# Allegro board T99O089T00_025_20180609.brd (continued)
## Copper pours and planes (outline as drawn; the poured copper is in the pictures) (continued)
(no net) on T18: 49.51,109.04 56.87,109.04 57.38,108.53 57.38,107.13 57.13,106.88 49.64,106.88 49.38,107.13 49.38,108.91
(no net) on T18: 49.08,90.08 45.96,90.08 45.36,89.49 45.36,79.55 43.2,77.39 43.2,68.43 44.11,67.52 51.7,67.52 52,67.82 52,76.89 49.45,79.44 49.45,89.72
(no net) on T18: 48.15,186.53 48.42,186.26 55.27,186.26 56.46,187.44 56.46,190.62 58.35,192.51 59.89,194.05 72.24,206.4 86.28,206.4 87.52,207.64 104.05,207.64 105.12,208.7 105.12,211.35 104.73,211.75 65.69,211.75 52.56,198.61 52.56,197.71 48.15,193.29
(no net) on T18: 7.08,90.33 7.08,97.55 8.02,98.48 25.32,98.48 25.72,98.09 25.72,90.41 25.47,90.16 7.26,90.16
(no net) on T18: 152.27,138.05 164.08,138.05 164.97,137.16 164.97,123.83 163.19,122.05 153.42,122.05 150.88,124.59 150.88,127.38 151.68,128.18 151.68,129.31 151.87,129.5 153.13,129.5 153.27,129.36 153.27,128.52 154.52,127.27 158.95,127.27 159.49,127.82 159.49,133.28 158.96,133.8 158.9,133.87 152.88,133.87 151.86,134.88 151.86,137.64
(no net) on T18: 57.13,104.72 56.87,104.47 50.14,104.47 49.89,104.72 49.89,106.37 50.27,106.75 57.13,106.75
(no net) on T18: 196.34,131.32 198.75,128.91 202.31,128.91 204.47,126.75 204.47,125.86 204.22,125.6 196.22,125.6 194.56,127.25 194.56,131.65 194.59,131.67 194.59,132.23 194.82,132.46 196.22,132.46 196.34,132.33
(no net) on G19: 1.39,0.51 1,0.51 0.65,0.65 0.51,1 0.51,207.78 0.51,208.98 0.65,209.33 1,209.47 2.2,209.47 38.51,209.47 39.55,209.91 39.99,210.95 39.99,214.03 39.99,214.03 39.99,214.83 40.14,215.18 40.48,215.32 41.29,215.32 312.38,215.32 312.5,215.32 312.85,215.18 312.99,214.83 312.99,14.06 312.88,14.06 312.17,13.76 311.87,13.05 311.87,10.55 312.17,9.84 312.88,9.54 312.99,9.54 312.99,5.57 312.99,4.97 312.85,4.62 312.5,4.48 311.9,4.48 288.55,4.48 288.55,4.11 83.6,4.11 82.91,4.11 82.56,4.25 82.42,4.6 82.42,5.29 82.42,10.48 81.97,11.52 80.94,11.96 63.41,11.96 62.64,11.73 62.1,11.14 43.51,11.14 42.47,10.7 42.03,9.66 42.03,1.47 42.03,1 41.89,0.65 41.54,0.51 41.07,0.51 ; 19 cut-outs
5P49V_VDDO on BOTTOM (solid shape): 145.78,118.35 145.78,117.03 145.74,116.98 143.4,116.98 143.18,117.28 142.9,117.51 142.9,118.39 143.06,118.56 145.57,118.56
5P49V_VDDO on T05 (solid shape): outline of 468 points within 137.63,117.83 144.35,124.8
DDR3_BMC_MVREF on BOTTOM (solid shape): outline of 673 points within 50.02,109.18 58,113.68
QSFP28_P1_VCC on TOP (solid shape): 310.57,79.61 310.75,79.54 310.82,79.36 310.82,72.31 310.71,72.19 309.56,72.19 309.4,72.35 309.4,79.36 309.48,79.54 309.66,79.61
QSFP28_P1_VCCRX on TOP (solid shape): 303.71,79.6 303.89,79.53 303.96,79.35 303.96,73.1 303.96,73.1 303.96,71.72 303.78,71.54 302.71,71.54 302.54,71.7 302.54,79.35 302.61,79.53 302.79,79.6
QSFP28_P2_VCC on TOP (solid shape): 294.28,79.22 294.46,79.15 294.53,78.97 294.53,72.19 294.86,71.87 294.86,71.27 294.61,71.02 293.27,71.02 293.11,71.18 293.11,78.97 293.18,79.15 293.36,79.22
QSFP28_P2_VCCTX on TOP (solid shape): 301.3,79.31 301.48,79.23 301.55,79.05 301.55,71.43 301.24,71.12 299.99,71.12 299.79,71.32 299.79,72.08 300.13,72.42 300.13,79.05 300.21,79.23 300.39,79.31
SFP+_P00_RXVCC on TOP (solid shape): 99.84,71.07 99.84,63.85 99.28,63.29 96.88,63.29 96.84,63.32 96.84,66.06 98.02,67.24 98.02,71.15 98.12,71.25 99.66,71.25
SFP+_P00_TXVCC on TOP (solid shape): 90.47,70.79 90.47,66.93 91.18,66.22 91.18,63.3 90.99,63.11 88.95,63.11 88.67,63.39 88.67,70.79 88.72,70.85 90.41,70.85
SFP+_P01_RXVCC on BOTTOM (solid shape): outline of 1433 points within 83.5,47.07 91.39,70.85
SFP+_P01_TXVCC on BOTTOM (solid shape): outline of 1321 points within 91.32,45.4 99.84,71.25
SFP+_P02_RXVCC on TOP (solid shape): 111.92,71.07 111.92,63.85 111.35,63.29 108.96,63.29 108.92,63.32 108.92,66.06 110.1,67.24 110.1,71.15 110.2,71.25 111.74,71.25
SFP+_P02_TXVCC on TOP (solid shape): 102.55,71.05 102.55,66.93 103.26,66.22 103.26,63.3 103.07,63.11 101.03,63.11 100.75,63.39 100.75,71.01 100.9,71.16 102.43,71.16
SFP+_P03_RXVCC on BOTTOM (solid shape): outline of 1409 points within 98.38,47.05 105.67,71.16
SFP+_P03_TXVCC on BOTTOM (solid shape): outline of 1297 points within 105.58,45.11 111.92,71.25
SFP+_P04_RXVCC on TOP (solid shape): 123.99,70.82 123.99,63.22 123.71,62.93 121.09,62.93 121,63.02 121,65.81 122.17,66.99 122.17,70.89 122.28,71 123.82,71
SFP+_P04_TXVCC on TOP (solid shape): 114.63,70.79 114.63,66.68 115.34,65.97 115.34,63.14 115.21,63.01 113.06,63.01 112.82,63.24 112.82,70.76 112.97,70.91 114.51,70.91
SFP+_P05_RXVCC on BOTTOM (solid shape): outline of 1568 points within 112.82,46.82 119.94,70.91
SFP+_P05_TXVCC on BOTTOM (solid shape): outline of 1262 points within 119.8,44.95 127.25,71
SFP+_P06_RXVCC on TOP (solid shape): 136.07,70.82 136.07,63.22 135.78,62.93 133.17,62.93 133.08,63.02 133.08,65.81 134.25,66.99 134.25,70.89 134.35,71 135.89,71
SFP+_P06_TXVCC on TOP (solid shape): 126.7,70.79 126.7,66.68 127.41,65.97 127.41,63.14 127.26,62.99 125.15,62.99 124.9,63.24 124.9,70.76 125.05,70.91 126.59,70.91
SFP+_P07_RXVCC on BOTTOM (solid shape): outline of 1524 points within 124.9,46.62 134.25,70.91
SFP+_P07_TXVCC on BOTTOM (solid shape): outline of 1267 points within 133.08,44.79 139.72,71
SFP+_P08_RXVCC on TOP (solid shape): 152.01,71.33 152.01,64.11 151.45,63.54 149.05,63.54 149.02,63.58 149.02,66.32 150.19,67.49 150.19,71.4 150.3,71.5 151.84,71.5
SFP+_P08_TXVCC on TOP (solid shape): 142.65,71.3 142.65,67.19 143.36,66.48 143.36,63.55 143.17,63.36 141.12,63.36 140.84,63.64 140.84,71.27 140.99,71.42 142.53,71.42
SFP+_P09_RXVCC on BOTTOM (solid shape): outline of 1549 points within 140.84,47.07 148.42,71.42
SFP+_P09_TXVCC on BOTTOM (solid shape): outline of 1151 points within 148.35,45.4 153.73,71.5
SFP+_P10_RXVCC on TOP (solid shape): 164.09,70.94 164.09,63.72 163.53,63.16 161.13,63.16 161.1,63.2 161.1,65.94 162.27,67.11 162.27,71.02 162.37,71.12 163.91,71.12
SFP+_P10_TXVCC on TOP (solid shape): 154.72,71.3 154.72,67.19 155.43,66.48 155.43,63.55 155.24,63.36 153.2,63.36 152.92,63.64 152.92,71.27 153.07,71.42 154.61,71.42
SFP+_P11_RXVCC on BOTTOM (solid shape): outline of 1443 points within 152.92,47.05 162.69,71.42
SFP+_P11_TXVCC on BOTTOM (solid shape): outline of 1192 points within 161.1,45.11 167.75,71.12
SFP+_P12_RXVCC on TOP (solid shape): 176.17,71.07 176.17,63.47 175.88,63.19 173.26,63.19 173.17,63.28 173.17,66.06 174.35,67.24 174.35,71.15 174.45,71.25 175.99,71.25
SFP+_P12_TXVCC on TOP (solid shape): 166.8,71.05 166.8,66.93 167.51,66.22 167.51,63.39 167.38,63.26 165.23,63.26 165,63.5 165,71.01 165.15,71.16 166.69,71.16
SFP+_P13_RXVCC on BOTTOM (solid shape): outline of 1268 points within 165,46.82 176.96,71.16
SFP+_P13_TXVCC on BOTTOM (solid shape): outline of 1137 points within 173.17,44.95 182.23,71.25
SFP+_P14_RXVCC on TOP (solid shape): 188.25,71.07 188.25,63.53 187.99,63.27 185.32,63.27 185.25,63.34 185.25,66.06 186.43,67.24 186.43,71.15 186.53,71.25 188.07,71.25
SFP+_P14_TXVCC on TOP (solid shape): 178.88,71.05 178.88,66.93 179.59,66.22 179.59,63.4 179.44,63.25 177.32,63.25 177.07,63.5 177.07,71.01 177.22,71.16 178.76,71.16
SFP+_P15_RXVCC on BOTTOM (solid shape): outline of 1546 points within 177.07,46.62 191.27,71.16
SFP+_P15_TXVCC on BOTTOM (solid shape): outline of 1296 points within 185.25,44.79 198.81,71.25
SFP+_P16_RXVCC on TOP (solid shape): 216.12,71.33 216.12,64.11 215.56,63.54 213.16,63.54 213.12,63.58 213.12,66.32 214.3,67.49 214.3,71.4 214.4,71.5 215.94,71.5
SFP+_P16_TXVCC on TOP (solid shape): 206.75,71.3 206.75,67.19 207.46,66.48 207.46,63.55 207.27,63.36 205.23,63.36 204.95,63.64 204.95,71.27 205.1,71.42 206.64,71.42
SFP+_P17_RXVCC on BOTTOM (solid shape): 206.7,71.06 206.7,66.94 207.41,66.23 207.41,63.34 207.36,63.29 205.08,63.29 204.9,63.47 204.9,71.02 205.05,71.17 206.59,71.17
SFP+_P17_TXVCC on BOTTOM (solid shape): 216.12,71.33 216.12,63.51 215.92,63.31 213.12,63.31 213.12,66.32 214.3,67.49 214.3,71.4 214.4,71.5 215.94,71.5
SFP+_P18_RXVCC on TOP (solid shape): 228.2,70.94 228.2,63.72 227.63,63.16 225.24,63.16 225.2,63.2 225.2,65.94 226.38,67.11 226.38,71.02 226.48,71.12 228.02,71.12
SFP+_P18_TXVCC on TOP (solid shape): 218.83,71.3 218.83,67.19 219.54,66.48 219.54,63.55 219.35,63.36 217.31,63.36 217.03,63.64 217.03,71.27 217.18,71.42 218.71,71.42
SFP+_P19_RXVCC on BOTTOM (solid shape): 218.83,71.3 218.83,67.19 219.54,66.48 219.54,63.19 219.51,63.12 219.43,63.09 219.01,62.96 218.86,62.55 218.83,62.47 218.75,62.44 217.32,62.44 217.03,62.74 217.03,71.27 217.18,71.42 218.71,71.42
SFP+_P19_TXVCC on BOTTOM (solid shape): 228.2,70.94 228.2,61.68 227.87,61.35 225.4,61.35 225.2,61.55 225.2,62.57 225.68,62.57 225.68,62.51 225.69,62.44 225.7,62.38 225.73,62.32 225.76,62.27 225.79,62.21 225.84,62.17 225.89,62.13 225.94,62.09 226,62.06 226.06,62.04 226.12,62.03 226.19,62.03 226.25,62.03 226.31,62.04 226.37,62.06 226.43,62.09 226.49,62.13 226.54,62.17 226.58,62.21 226.62,62.27 226.65,62.32 226.67,62.38 226.69,62.44 226.7,62.51 226.7,62.57 226.69,62.63 226.67,62.7 226.65,62.75 226.62,62.81 226.58,62.86 226.54,62.91 226.49,62.95 226.43,62.98 226.37,63.01 226.31,63.03 226.25,63.04 226.19,63.05 226.12,63.04 226.06,63.03 226,63.01 225.94,62.98 225.89,62.95 225.84,62.91 225.79,62.86 225.76,62.81 225.73,62.75 225.7,62.7 225.69,62.63 225.68,62.57 225.2,62.57 225.2,65.94 226.38,67.11 226.38,71.02 226.48,71.12 228.02,71.12
SFP+_P20_RXVCC on TOP (solid shape): 240.27,71.07 240.27,63.47 239.99,63.19 237.37,63.19 237.28,63.28 237.28,66.06 238.45,67.24 238.45,71.15 238.56,71.25 240.1,71.25
SFP+_P20_TXVCC on TOP (solid shape): 230.91,71.05 230.91,66.93 231.62,66.22 231.62,63.39 231.49,63.26 229.34,63.26 229.1,63.5 229.1,71.01 229.25,71.16 230.79,71.16
SFP+_P21_RXVCC on BOTTOM (solid shape): 230.91,71.05 230.91,66.93 231.62,66.22 231.62,63.05 231.57,62.97 231.48,62.96 230.78,62.49 231.48,62.01 231.57,62 231.62,61.92 231.62,61.09 231.27,60.75 229.49,60.75 229.1,61.14 229.1,71.01 229.25,71.16 230.79,71.16
SFP+_P21_TXVCC on BOTTOM (solid shape): 240.27,71.07 240.27,61.93 239.75,61.41 237.62,61.41 237.28,61.75 237.28,61.88 237.31,61.95 237.38,61.98 237.89,62.49 237.38,62.99 237.31,63.02 237.28,63.1 237.28,66.06 238.45,67.24 238.45,71.15 238.56,71.25 240.1,71.25
SFP+_P22_RXVCC on TOP (solid shape): 252.35,71.07 252.35,63.53 252.09,63.27 249.42,63.27 249.36,63.34 249.36,66.06 250.53,67.24 250.53,71.15 250.63,71.25 252.17,71.25
SFP+_P22_TXVCC on TOP (solid shape): 242.98,71.05 242.98,66.93 243.69,66.22 243.69,63.4 243.54,63.25 241.43,63.25 241.18,63.5 241.18,71.01 241.33,71.16 242.87,71.16
SFP+_P23_RXVCC on BOTTOM (solid shape): 242.97,71.05 242.97,66.93 243.68,66.22 243.68,62.23 243.41,61.96 241.44,61.96 241.17,62.23 241.17,71.01 241.32,71.16 242.86,71.16
SFP+_P23_TXVCC on BOTTOM (solid shape): 252.34,71.07 252.34,63.87 252.36,63.85 252.36,62.57 252.09,62.3 249.62,62.3 249.34,62.58 249.34,66.06 250.52,67.24 250.52,71.15 250.62,71.25 252.16,71.25
SFP+_P24_RXVCC on TOP (solid shape): 264.51,70.99 264.51,63.77 263.95,63.21 261.55,63.21 261.52,63.24 261.52,65.98 262.69,67.16 262.69,71.06 262.8,71.17 264.34,71.17
SFP+_P24_TXVCC on TOP (solid shape): 255.15,71.35 255.15,67.23 255.86,66.52 255.86,63.6 255.67,63.41 253.62,63.41 253.34,63.69 253.34,71.31 253.49,71.46 255.03,71.46
SFP+_P25_RXVCC on BOTTOM (solid shape): 255.15,71.35 255.15,67.23 255.86,66.52 255.86,62.23 255.34,61.72 253.6,61.72 253.34,61.97 253.34,71.31 253.49,71.46 255.03,71.46
SFP+_P25_TXVCC on BOTTOM (solid shape): 264.51,70.99 264.51,63.53 264.51,61.98 264.03,61.5 261.7,61.5 261.52,61.69 261.52,62.21 261.56,62.21 261.93,62.66 261.56,63.11 261.52,63.12 261.52,65.98 262.69,67.16 262.69,71.06 262.8,71.17 264.34,71.17
SFP+_P26_RXVCC on TOP (solid shape): 276.59,70.99 276.59,63.77 276.03,63.21 273.63,63.21 273.6,63.24 273.6,65.98 274.77,67.16 274.77,71.06 274.82,71.11 276.47,71.11
SFP+_P26_TXVCC on TOP (solid shape): 267.22,71.35 267.22,67.23 267.93,66.52 267.93,63.6 267.74,63.41 265.7,63.41 265.42,63.69 265.42,71.31 265.57,71.46 267.11,71.46
SFP+_P27_RXVCC on BOTTOM (solid shape): 267.22,71.35 267.22,67.23 267.93,66.52 267.93,63.3 267.89,63.21 267.79,63.2 267.15,62.78 267.79,62.37 267.89,62.36 267.93,62.27 267.93,61.89 267.65,61.61 265.72,61.61 265.42,61.92 265.42,71.31 265.57,71.46 267.11,71.46
SFP+_P27_TXVCC on BOTTOM (solid shape): 276.59,70.99 276.59,62 276.28,61.69 274.33,61.69 273.83,62.19 273.8,62.28 273.87,62.36 274.15,62.87 273.7,63.24 273.63,63.27 273.6,63.34 273.6,65.98 274.77,67.16 274.77,71.06 274.87,71.17 276.41,71.17
VFLT_P1V8_JA_VDD on BOTTOM (solid shape): 162.41,139.91 162.41,136.51 162.41,135.59 162.41,134.87 162.28,134.75 161.01,134.75 160.9,134.85 160.9,139.84 161.05,139.99 162.33,139.99
VFLT_P1V8_JA_VDD on T07 (solid shape): outline of 489 points within 155.13,125.03 162.69,135.95
VFLT_P1V8_SMU_VDDC on TOP (solid shape): 4.69,89.37 4.69,81.76 4.47,81.54 2.94,81.54 2.6,81.88 2.6,89.38 2.8,89.58 4.48,89.58
VFLT_P1V8_SMU_VDDC on BOTTOM (solid shape): 5.49,89.27 5.49,87.48 5.26,87.26 3.27,87.26 3.04,87.48 3.04,89.27 3.33,89.57 5.19,89.57
VFLT_P1V8_SMU_VDDC on P10 (solid shape): outline of 439 points within 3.29,85.01 17.68,89.87
VFLT_P3V3_5P49V_VDDA on BOTTOM (solid shape): 135.88,121.06 137.3,121.06 137.34,121.02 137.34,120.17 137.57,119.94 138.24,119.94 138.54,119.65 138.54,118.75 138.31,118.53 135.19,118.53 134.94,118.78 134.94,121.11 135.04,121.22 135.73,121.22
VFLT_P3V3_5P49V_VDDD on TOP (solid shape): 141.48,130.23 141.48,129.15 141.3,128.96 137.37,128.96 137.29,129.05 137.29,130.24 137.41,130.36 141.34,130.36
VFLT_P3V3_BMC_HPLLAV33 on T14 (solid shape): outline of 1277 points within 45.11,102.08 58.19,108.94
VFLT_P3V3_BMC_MPLLDV12 on T18 (solid shape): outline of 392 points within 49.38,106.88 57.38,109.04
VFLT_P3V3_BMC_USB2AV33 on BOTTOM (solid shape): outline of 641 points within 50.82,105.93 57.26,109.38
VFLT_P3V3_BMC_VPLLAV12 on T18 (solid shape): outline of 271 points within 49.89,104.47 57.13,106.63
VFLT_P3V3_CLK_25M on TOP (solid shape): 165.45,86.08 165.45,83.91 165.41,83.79 165.4,83.66 165.4,83.64 165.33,83.58 164.82,83.58 164.82,83.55 162.92,83.55 162.56,83.92 161.61,83.92 161.58,83.95 161.58,84.48 161.95,84.86 161.99,84.89 162.03,84.94 162.62,85.53 163.6,85.53 164.2,86.13 165.4,86.13
VFLT_P3V3_CLK_156.25MHZ on TOP (solid shape): 157.17,115.73 157.23,115.64 157.23,114.96 157.35,114.85 157.35,114.37 157.21,114.25 157.09,114.12 155.65,114.12 155.65,114.13 154.74,114.13 154.74,114.12 154.17,114.12 154.17,114.13 153.31,114.13 153.28,114.23 153.24,114.32 153.24,115.5 153.34,115.6 154.39,115.6 155.16,115.23 155.99,115.4 156.56,115.44 157.07,115.72
VFLT_P3V3_CPLD_VDDA on BOTTOM (solid shape): 112.46,120.81 112.46,118.45 112.25,118.24 111.28,118.24 111.28,118.32 111.23,118.32 111.23,118.24 107.63,118.24 107.6,118.28 107.6,120.77 107.89,121.07 112.2,121.07
VFLT_P3V3_CPLD_VDDA on T16 (solid shape): outline of 4346 points within 110.87,118.27 118.49,134.1
VFLT_P3V3_GNSS_VCC on BOTTOM (solid shape): 17.25,42.45 17.25,40.94 17.18,40.88 16,40.88 15.68,40.96 15.36,40.88 10.74,40.88 10.58,41.04 10.58,42.15 10.72,42.3 15.65,42.3 15.86,42.5 15.87,42.51 15.96,42.54 16.05,42.59 17.11,42.59
VFLT_P3V3_JA_VDDA on TOP (solid shape): 152.55,138.94 152.55,136.17 152.39,136.01 150.93,136.01 150.71,136.23 150.71,137.7 150.55,137.86 149.07,137.86 148.92,138.02 148.92,139.12 148.98,139.18 152.3,139.18
VFLT_P3V3_JA_VDDA on T18 (solid shape): outline of 1785 points within 150.88,122.05 164.97,138.05
VFLT_P3V3_JA_VDDO on BOTTOM (solid shape): 165.18,127.83 165.06,127.38 165.41,127.06 165.45,127.05 165.45,125.61 165.43,125.59 164.03,125.59 163.88,125.43 160.79,125.43 160.64,125.59 160.64,126.73 160.87,126.97 160.87,127.87 161.02,128.01 165,128.01
VFLT_P3V3_JA_VDDO on P10 (solid shape): outline of 455 points within 156.83,125.53 162.2,135.09
VFLT_P3V3_OCXO_DPLL on TOP (solid shape): 31.12,140.28 31.12,138.33 30.94,138.16 27.44,138.16 27.31,138.28 27.31,140.33 27.51,140.52 30.87,140.52
VFLT_P3V3_OCXO_DPLL on BOTTOM (solid shape): 20.34,140.82 20.34,140.08 20.68,139.74 26.24,139.74 26.99,140.5 30.91,140.5 31.09,140.32 31.09,138.17 30.59,137.67 18.71,137.67 18.39,137.99 18.39,140.96 18.42,141 20.16,141
VFLT_P3V3_OSC_25M_BUF on TOP (solid shape): 155.36,86.8 155.36,84.74 155.3,84.69 153.99,84.69 153.86,84.82 153.86,86.75 154.06,86.95 155.2,86.95
VFLT_P3V3_OSC_25M_BUF on TOP (solid shape): 163.35,97.29 164.79,97.29 164.79,97.28 165.7,97.28 165.7,97.29 166.31,97.29 166.31,97.28 167.2,97.28 167.3,97.18 167.3,96.13 167.08,95.91 162.81,95.91 162.48,95.58 162.48,94.88 162.23,94.63 160.94,94.63 160.87,94.7 160.87,97.64 161.03,97.8 162.84,97.8
VFLT_P3V3_OSC_25M_BUF on T05 (solid shape): outline of 305 points within 154.04,86.28 164.9,97.5
VFLT_P3V3_SMU_VDDA1 on BOTTOM (solid shape): 12.8,102.05 16.42,102.05 16.51,101.96 16.51,99.94 16.35,99.78 13.95,99.78 13.34,100.14 12.72,99.78 9.8,99.78 9.24,100.35 9.24,103.39 9.28,103.43 11.43,103.43
VFLT_P3V3_SMU_VDDA1 on T03 (solid shape): outline of 634 points within 15.1,96.96 23.71,102
VFLT_P3V3_SMU_VDDA2 on BOTTOM (solid shape): 33.94,99.19 33.94,96.59 33.67,96.32 30.75,96.32 30.74,96.35 30.31,96.65 29.88,96.35 29.87,96.32 26.18,96.32 25.91,96.59 25.91,99.15 26.1,99.34 33.79,99.34
VFLT_P3V3_SMU_VDDA2 on P10 (solid shape): outline of 2294 points within 17.13,88.7 26.42,99.7
VFLT_P3V3_SMU_VDDAO on TOP (solid shape): 7.87,97.04 7.87,90.32 7.61,90.05 5.69,90.05 5.65,90.09 5.65,97.13 5.75,97.23 7.68,97.23
VFLT_P3V3_SMU_VDDAO on BOTTOM (solid shape): 7.75,92.54 7.75,90.41 7.47,90.13 5.66,90.13 5.4,90.39 5.4,92.5 5.71,92.8 7.48,92.8
VFLT_P3V3_SMU_VDDAO on T18 (solid shape): outline of 3259 points within 7.08,90.16 25.72,98.48
VFLT_P3V3_SMU_VDDC on TOP (solid shape): 30.28,103.61 30.28,101.9 30.08,101.7 27.84,101.7 27.84,101.71 27.71,101.72 27.59,101.71 27.58,101.7 26.87,101.7 26.77,101.71 26.66,101.7 23.45,101.7 23.24,101.91 23.24,103.64 23.28,103.68 30.21,103.68
VFLT_P3V3_SMU_VDDC on T14 (solid shape): outline of 1714 points within 19.5,90.9 25.93,102.91
VFLT_P3V3_SMU_VDDO on TOP (solid shape): 13.66,102.97 13.66,99.26 13.46,99.06 10.97,99.06 9.5,100.53 6.12,100.53 5.89,100.76 5.89,102.94 5.98,103.04 13.59,103.04
VFLT_P3V3_SMU_VDDO on T16 (solid shape): outline of 297 points within 10.35,90.05 21.96,100.05
VFLT_VP1P0_MAC_NIF_TRXVDD on BOTTOM (solid shape): outline of 663 points within 205.87,84.4 219.88,103.63
VFLT_VP1P0_MAC_NIF_TRXVDD on T03 (solid shape): outline of 10745 points within 207.27,94.22 233.53,111.45
VFLT_VP1P0_MAC_NIFE_TRXVDD0 on BOTTOM (solid shape): 198.12,97.58 198.12,94.54 197.99,94.42 189.61,94.42 189.36,94.67 189.36,99.29 189.62,99.56 196.14,99.56
VFLT_VP1P0_MAC_NIFE_TRXVDD0 on BOTTOM (solid shape): 195.43,108.94 195.43,107.29 195.4,107.26 193.46,107.26 193.34,107.38 193.34,108.17 193.67,108.5 193.67,108.96 193.81,109.1 195.26,109.1
VFLT_VP1P0_MAC_NIFE_TRXVDD0 on T03 (solid shape): outline of 6124 points within 189.36,94.16 207.83,114.86
VFLT_VP1P0_MAC_NIFE_TRXVDD1 on BOTTOM (solid shape): outline of 3191 points within 224.1,93.55 237.11,119.21
VFLT_VP1P0_MAC_NIFE_TRXVDD1 on T05 (solid shape): outline of 4685 points within 224.53,99.78 236.67,118.8
VFLT_VP1P0_MAC_PCIE_TRXVDD on BOTTOM (solid shape): 197.54,119.32 197.86,119.13 198.18,119.32 198.53,119.32 198.55,119.3 198.6,119.23 198.66,119.18 198.68,119.17 198.68,118.88 198.44,118.5 198.68,118.12 198.68,116.83 198.6,116.76 198.53,116.69 198.21,116.69 198.18,116.73 198.14,116.77 197.86,117.06 197.86,117.3 197.76,117.36 197.73,117.39 197.71,117.43 197.65,117.56 197.39,117.56 197.39,117.65 197.33,117.65 197.33,117.56 197.07,117.56 197.01,117.43 196.99,117.39 196.96,117.36 196.86,117.3 196.86,116.8 196.89,116.77 196.9,116.72 196.85,116.69 196.27,116.69 195.13,117.83 192.43,117.83 192.4,117.86 192.4,118.76 192.56,118.92 195.66,118.92 196.08,118.5 196.85,118.5 197.04,118.69 197.04,119.12 197.24,119.32
VFLT_VP1P0_MACS_PCIE_PLL on BOTTOM (solid shape): 195.37,120.39 195.42,120.39 195.42,120.47 196.51,120.47 196.7,120.28 196.7,119.89 196.3,119.49 196.16,119.49 195.96,119.29 195.96,119.25 192.39,119.25 192.24,119.4 192.24,120.44 192.27,120.47 195.37,120.47
VFLT_VP1P0_MACS_TSC_PLL on BOTTOM (solid shape): 245.87,122.94 245.87,117.98 245.51,117.62 237.07,117.62 236.98,117.71 236.98,119.18 237.11,119.31 237.52,119.31 237.66,119.46 237.83,119.46 237.84,119.45 238.51,119.75 238.03,120.31 237.96,120.33 237.92,120.41 237.92,120.53 238.16,120.76 239.64,120.76 239.67,120.79 239.86,120.79 239.95,120.88 239.95,123.2 240.36,123.6 245.2,123.6
VFLT_VP1P0_MACS_TSC_PLL on T03 (solid shape): outline of 9380 points within 204.57,111.25 239.72,122.23
VFLT_VP1P0_PHY1_SFI_PLL on TOP (solid shape): 148.4,105.66 148.4,102.2 148.28,102.08 144.49,102.08 144.24,102.33 144.24,104.54 144.44,104.74 145.93,104.74 146.94,105.76 148.31,105.76
VFLT_VP1P0_PHY1_SFI_PLL on BOTTOM (solid shape): 147.92,104.26 147.92,102.23 147.59,101.9 144.3,101.9 144.18,102.03 144.18,104.13 144.49,104.44 147.74,104.44
VFLT_VP1P0_PHY1_SFI_PLL on T05 (solid shape): outline of 2174 points within 126.95,90.96 145.52,103.27
VFLT_VP1P0_PHY1_SFI_PWR on TOP (solid shape): 147.66,101.41 147.66,93.87 147.64,93.84 143.38,93.84 143.24,93.98 143.25,94 143.19,94.3 142.94,94.46 142.9,94.46 142.9,101.34 143.16,101.6 147.47,101.6
VFLT_VP1P0_PHY1_SFI_PWR on BOTTOM (solid shape): 147.88,100.79 147.88,97.82 147.66,97.6 147.66,93.86 147.64,93.84 147.64,93.73 147.04,93.13 143.39,93.13 143.1,93.43 143.1,93.77 143.26,94.08 143.1,94.39 143.1,100.83 143.37,101.11 147.57,101.11
VFLT_VP1P0_PHY1_SFI_PWR on P10 (solid shape): outline of 6118 points within 120.21,86.24 146.8,97.44
VFLT_VP1P0_PHY1_XFI_PLL on BOTTOM (solid shape): 133.99,107.4 133.99,106.02 133.76,105.78 125.75,105.78 125.39,106.13 125.39,107.21 125.69,107.51 133.89,107.51
VFLT_VP1P0_PHY1_XFI_PLL on T07 (solid shape): outline of 394 points within 126.66,102.08 130.09,106.32
VFLT_VP1P0_PHY1_XFI_PWR on BOTTOM (solid shape): 139.83,112.75 139.83,101.38 139.62,101.17 138.9,101.17 138.56,100.83 137.94,100.83 137.69,101.09 137.69,110.67 137.46,110.9 137.46,112.9 137.65,113.09 139.48,113.09
VFLT_VP1P0_PHY1_XFI_PWR on T03 (solid shape): outline of 3364 points within 120.07,99.5 139.98,105
VFLT_VP1P0_PHY3_DVDD on BOTTOM (solid shape): 274.66,94.79 274.66,89.78 274.39,89.51 259.46,89.51 259.37,89.6 259.37,90.95 269.93,90.95 269.93,90.89 269.94,90.84 269.96,90.78 269.98,90.72 270.01,90.67 270.05,90.62 270.09,90.58 270.14,90.54 270.19,90.51 270.24,90.49 270.3,90.48 270.36,90.47 270.42,90.47 270.48,90.48 270.54,90.49 270.59,90.51 270.64,90.54 270.69,90.58 270.73,90.62 270.77,90.67 270.8,90.72 270.82,90.78 270.84,90.84 270.85,90.89 270.85,90.95 270.84,91.01 270.82,91.07 270.8,91.13 270.77,91.18 270.73,91.23 270.69,91.27 270.64,91.31 270.59,91.34 270.54,91.36 270.48,91.37 270.42,91.38 270.36,91.38 270.3,91.37 270.24,91.36 270.19,91.34 270.14,91.31 270.09,91.27 270.05,91.23 270.01,91.18 269.98,91.13 269.96,91.07 269.94,91.01 269.93,90.95 259.37,90.95 259.37,93.33 260.99,94.95 274.5,94.95
VFLT_VP1P0_PHY3_DVDD on P10 (solid shape): outline of 5445 points within 271.6,82.12 286.35,95.68
VFLT_VP1P0_PHY3_PLL on BOTTOM (solid shape): 295.99,103.49 295.99,100.27 295.72,100 294.03,100 293.79,100.25 293.79,101.62 293.46,101.95 290.4,101.95 290.08,102.03 289.76,101.95 288.86,101.95 288.6,102.22 288.6,103.92 288.63,103.96 295.52,103.96
VFLT_VP1P0_PHY3_PLL on P10 (solid shape): outline of 2606 points within 279.62,96.05 295.03,103.83
VFLT_VP1P0_PHY3_XFI_RX on BOTTOM (solid shape): 269.56,102.35 269.56,99.93 270.17,99.33 272.23,99.33 272.38,99.18 272.38,97.2 272.23,97.05 265.97,97.05 265.6,97.42 265.6,100.54 264.91,101.24 256.38,101.24 256.1,101.52 256.1,106.31 256.53,106.74 265.17,106.74
VFLT_VP1P0_PHY3_XFI_RX on T14 (solid shape): outline of 8569 points within 270.23,84.97 288.77,102.27
VFLT_VP1P0_PHY3_XFI_TX on BOTTOM (solid shape): 286.01,104.41 286.01,103.89 286.54,103.37 287.77,103.37 288.04,103.09 288.04,102.07 287.78,101.81 284.4,101.81 284.03,102.17 279.7,102.17 279.54,102.34 279.54,104.31 279.71,104.48 285.94,104.48
VFLT_VP1P0_PHY3_XFI_TX on T05 (solid shape): outline of 3029 points within 280.47,87.95 288.17,103.09
VFLT_VP1P8_MAC_VDDP on TOP (solid shape): 186.95,140.59 186.95,139.82 186.94,139.75 186.95,139.68 186.95,139.22 186.62,138.88 185.31,138.88 185.26,138.93 185.26,140.85 185.59,141.17 186.37,141.17
VFLT_VP1P8_MAC_VDDP on P10 (solid shape): outline of 4089 points within 185.42,122.99 205.11,141.24
VFLT_VP1P8_MACS_BS01_PLL on T18 (solid shape): outline of 1352 points within 194.56,125.6 204.47,132.46
VFLT_VP1P8_MACS_BS_PLL on BOTTOM (solid shape): 195.42,115.32 195.42,114.8 194.56,113.94 192.12,113.94 192.06,114 192.06,114.61 192.17,114.72 193.13,114.72 193.15,114.74 193.16,114.74 193.89,115.47 195.27,115.47
VFLT_VP1P8_MACS_BS_PLL on P10 (solid shape): outline of 1132 points within 194.4,114.27 202.31,119.59
VFLT_VP1P8_MACS_CORE_PLL on BOTTOM (solid shape): 233.9,120.46 236.2,120.46 236.28,120.38 236.28,119.65 236.16,119.52 233.44,119.52 233.07,119.89 232.86,119.89 232.61,119.8 232.47,119.56 232.46,119.52 232.26,119.52 232.25,119.56 231.98,119.87 231.58,119.77 231.33,119.52 231.3,119.52 231.09,119.73 231.09,120.71 231.24,120.85 233.5,120.85
VFLT_VP1P8_MACS_CORE_PLL on P10 (solid shape): outline of 1583 points within 216.47,118.19 234.95,121.64
VFLT_VP1P8_MACS_MCU_PLL on T14 (solid shape): outline of 565 points within 188.73,116.56 201.09,123.56
VFLT_VP1P8_MACS_NIF_PLL on BOTTOM (solid shape): 195.88,110.52 195.88,110.09 195.36,109.57 193.6,109.57 193.25,109.74 192.9,109.57 192.32,109.57 192.11,109.78 192.11,110.61 192.16,110.66 195.59,110.66 195.75,110.66
VFLT_VP1P8_MACS_NIF_PLL on P10 (solid shape): outline of 1741 points within 193.55,109.78 210.31,114.02
VFLT_VP1P8_MACS_NIFE0_PLL on BOTTOM (solid shape): 192.69,127.4 192.69,125.17 192.39,124.87 190.33,124.87 190.01,125.2 190.01,127.49 190.09,127.57 192.52,127.57
VFLT_VP1P8_MACS_NIFE0_PLL on T16 (solid shape): outline of 2134 points within 190.98,114.91 208.11,126.86
VFLT_VP1P8_MACS_NIFE1_PLL on BOTTOM (solid shape): 235.7,115.13 237.96,115.13 238.05,115.04 238.05,113.92 237.77,113.64 234.06,113.64 233.86,113.84 233.86,114.3 233.85,114.3 233.85,114.69 233.86,114.7 233.86,115.19 233.85,115.2 233.85,115.55 234.13,115.83 235,115.83
VFLT_VP1P8_MACS_NIFE1_PLL on P10 (solid shape): outline of 1594 points within 220.25,113.79 235.3,117.68
VFLT_VP1P8_MACS_SYNCE0_PLL on BOTTOM (solid shape): 195.31,130.03 195.31,128.06 195.05,127.8 192.91,127.8 192.76,127.95 192.76,130.08 192.8,130.12 195.23,130.12
VFLT_VP1P8_MACS_SYNCE0_PLL on T16 (solid shape): outline of 3345 points within 193.62,121.98 207.34,129.56
VFLT_VP1P8_MACS_SYNCE1_PLL on BOTTOM (solid shape): 193.18,135.99 194.1,135.99 194.1,135.99 194.88,135.99 195.14,135.72 195.14,135.05 194.73,134.63 191.39,134.63 191.16,134.4 190.77,134.4 190.51,134.66 190.51,135.05 190.85,135.39 191.4,135.39 191.65,135.64 191.65,135.95 191.68,135.99 192.57,135.99 192.57,135.99 193.18,135.99
VFLT_VP1P8_MACS_SYNCE1_PLL on P10 (solid shape): outline of 5465 points within 194.11,125.04 211.37,140.97
VFLT_VP1P25_MAC_NIF_TVDD on BOTTOM (solid shape): 225.5,100.37 225.71,100.37 225.75,100.33 225.75,98.54 227.07,97.21 227.07,93.02 228.19,91.91 228.19,90.26 228,90.07 223.12,90.07 221.77,91.42 221.77,99.65 222.53,100.41 225.46,100.41
VFLT_VP1P25_MAC_NIF_TVDD on P10 (solid shape): outline of 2551 points within 210.28,98.4 224.44,105.84
VFLT_VP1P25_PHY3_XFI_TRX on BOTTOM (solid shape): 274.58,106.42 274.86,106.12 275.26,106.17 275.3,106.19 275.6,105.88 276.88,105.88 277.27,105.5 277.27,104.24 277.52,103.98 278.47,103.98 278.82,103.64 278.82,102.32 278.54,102.05 276.7,102.05 276.06,102.47 275.42,102.05 275.17,102.05 274.7,102.52 274.7,103.24 273.63,104.3 268.4,104.3 268.22,104.49 268.22,106.3 268.37,106.45 274.57,106.45
VFLT_VP1P25_PHY3_XFI_TRX on T07 (solid shape): outline of 5024 points within 274.08,89.88 287.68,104.56
VFLT_VP3P3_MAC_VDDO on BOTTOM (solid shape): 186.07,114.92 186.44,114.73 186.8,114.92 187.87,114.92 188.2,114.59 188.2,112.96 187.92,112.68 183.13,112.68 183.04,112.77 183.04,114.23 183.73,114.92
VFLT_VP3P3_MAC_VDDO on BOTTOM (solid shape): outline of 1383 points within 195.54,126.27 202.1,133.81
VFLT_VP3P3_MAC_VDDO on T07 (solid shape): outline of 426 points within 195.45,121.48 201.53,123.85
VFLT_VP3P3_MAC_VDDO on T14 (solid shape): outline of 1659 points within 183.77,113.72 202.49,128.73
VOUT_HEATER_BMC on TOP (solid shape): 68.66,137.74 68.66,134.41 68.44,134.19 65.87,134.19 65.74,134.32 65.74,137.62 66.12,137.99 68.41,137.99
VOUT_HEATER_BMC on TOP (solid shape): 76.97,180.57 76.97,179.2 77.58,178.58 77.58,174.81 77.46,174.68 74.24,174.68 73.93,175 73.93,176.93 73.36,177.49 70.46,177.49 69.9,178.05 69.9,179.91 70.08,180.08 73.96,180.08 74.46,180.59 76.95,180.59
VOUT_HEATER_BMC on BOTTOM (solid shape): outline of 1788 points within 54.61,134.22 77.94,182.38
VP0P9_NIC1_VOUT on T07 (solid shape): outline of 974 points within 90.17,87.85 101.88,96.07
VP0P9_NIC1_VOUT on T14 (solid shape): outline of 1037 points within 88.9,88.11 101.73,97.59
VP1P5_NIC1_VOUT on T03 (solid shape): outline of 465 points within 90.42,84.2 99.44,92.26
VP1P5_NIC1_VOUT on T14 (solid shape): outline of 319 points within 87.63,85.15 94.75,94.04
VTT_DDR on TOP (solid shape): 263.77,150.34 263.8,150.31 264.29,149.83 264.29,145.16 264.13,145 262.94,145 262.81,145.14 262.81,150.15 262.97,150.3 262.97,150.45 263.04,150.53 263.59,150.53
VTT_DDR on TOP (solid shape): 202.21,173.43 206.39,173.43 206.72,173.76 220.59,173.76 220.7,173.64 220.7,172.55 220.4,172.25 220.38,172.25 220.21,172.22 220.06,172.14 217.81,172.14 217.49,172.26 217.18,172.14 215.43,172.14 215.38,172.14 215.33,172.14 210.01,172.14 209.65,171.77 209.65,170.79 209.63,170.77 198.93,170.77 198.83,170.87 198.83,173.53 199.06,173.76 201.88,173.76
VTT_DDR on TOP (solid shape): 270.07,139.52 270.07,136.57 269.82,136.57 269.82,134.72 270.07,134.72 270.07,134.42 269.82,134.42 269.82,132.57 270.07,132.57 270.07,118.14 269.97,118.05 267.78,118.05 267.54,118.29 267.54,122.86 267.23,123.17 266.68,123.17 266.57,123.27 266.57,126.12 267.1,126.12 267.1,126.06 267.11,126 267.13,125.95 267.15,125.89 267.18,125.84 267.22,125.79 267.26,125.75 267.31,125.71 267.36,125.68 267.41,125.66 267.47,125.64 267.53,125.64 267.59,125.64 267.65,125.64 267.71,125.66 267.76,125.68 267.81,125.71 267.86,125.75 267.9,125.79 267.94,125.84 267.97,125.89 267.99,125.95 268.01,126 268.02,126.06 268.02,126.12 268.01,126.18 267.99,126.24 267.97,126.3 267.94,126.35 267.9,126.4 267.86,126.44 267.81,126.47 267.76,126.5 267.71,126.53 267.65,126.54 267.59,126.55 267.53,126.55 267.47,126.54 267.41,126.53 267.36,126.5 267.31,126.47 267.26,126.44 267.22,126.4 267.18,126.35 267.15,126.3 267.13,126.24 267.11,126.18 267.1,126.12 266.57,126.12 266.57,139.53 266.69,139.65 269.94,139.65
VTT_DDR on TOP (solid shape): 230.86,173.66 232.71,173.66 232.71,173.72 233.01,173.72 233.01,173.66 234.86,173.66 234.86,173.72 247.83,173.72 248.18,173.37 248.18,171.15 247.78,170.75 246.85,170.75 246.85,170.99 246.84,171.07 246.83,171.1 247.02,171.29 247.1,172 246.39,171.92 245.91,171.44 245.91,171.17 245.87,171.04 245.86,170.75 233.67,170.75 233.58,170.8 233.59,170.9 233.21,171.61 232.82,170.9 232.83,170.8 232.74,170.75 230.59,170.75 230.59,170.89 230.5,170.96 230.47,170.99 230.45,171.03 230.39,171.16 230.12,171.16 230.12,171.24 230.07,171.24 230.07,171.16 229.81,171.16 229.75,171.03 229.73,170.99 229.69,170.96 229.59,170.89 229.49,170.96 229.45,170.99 229.43,171.03 229.37,171.16 229.11,171.16 229.11,171.24 229.06,171.24 229.06,171.16 228.79,171.16 228.73,171.03 228.71,170.99 228.68,170.96 228.59,170.89 228.59,170.81 228.52,170.75 228.15,170.75 227.98,170.92 227.98,173.66 228.05,173.72 230.86,173.72
VTT_DDR on BOTTOM (solid shape): 264.23,150.3 264.23,145.08 264.09,144.94 262.97,144.94 262.81,145.09 262.81,150.33 262.97,150.48 264.05,150.48
VTT_DDR on BOTTOM (solid shape): outline of 86 points within 198.83,170.77 220.77,173.76
VTT_DDR on BOTTOM (solid shape): 270.07,139.52 270.07,118.14 269.97,118.05 266.88,118.05 266.63,118.3 266.63,118.32 266.61,118.42 266.57,118.51 266.57,118.88 266.61,118.96 266.71,118.97 267.34,119.4 266.71,119.82 266.61,119.83 266.57,119.91 266.57,125.04 266.73,125.04 266.9,125.06 267.05,125.13 267.06,125.14 267.16,125.14 267.67,125.65 267.69,125.65 267.88,126.42 267.12,126.22 267.12,126.21 266.92,126.01 266.89,126.01 266.81,126.03 266.73,126.03 266.57,126.03 266.57,139.53 266.69,139.65 269.94,139.65
VTT_DDR on BOTTOM (solid shape): outline of 140 points within 227.98,170.75 249.45,173.72
VTT_DDR on T07 (solid shape): outline of 5308 points within 197.5,115.68 269.44,178.62
XTAL_SHIELD on TOP (solid shape): 151.58,132.29 151.58,131.12 151.3,130.84 149.19,130.84 149.17,130.86 149.17,132.6 149.13,132.65 147.16,132.65 147.06,132.54 147.06,130.49 147.54,130 148.91,130 148.96,129.96 148.96,128.16 149.05,128.07 150.83,128.07 150.92,128.16 150.92,129.72 151.02,129.83 151.36,129.83 151.49,129.69 151.49,128.44 150.3,127.25 146.84,127.25 146.12,127.97 146.12,132.79 146.91,133.58 150.28,133.58
XTAL_SHIELD on G02 (solid shape): 151.66,132.21 151.75,131.58 152.38,131.57 153.51,131.57 153.54,131.55 153.54,129.67 153.51,129.64 152.47,129.64 152.36,129.76 151.7,129.76 151.51,129.56 151.51,128.23 150.36,127.08 147.01,127.08 146.12,127.97 146.12,132.79 147.01,133.68 150.18,133.68
N65298280 on BOTTOM (solid shape): 137.35,88.59 137.35,86.33 137.24,86.22 128.19,86.22 127.84,85.87 127.84,84.91 127.3,84.38 124.04,84.38 123.83,84.6 123.83,86.66 124.21,87.04 127.01,87.04 127.47,87.51 127.47,88.64 127.7,88.86 137.08,88.86
N65298280 on T14 (solid shape): outline of 4258 points within 124.6,87.27 138.05,99.65
N68909145 on TOP (solid shape): 42.95,36.5 42.95,34.63 42.67,34.36 40.27,34.36 40.03,34.6 40.03,36.48 40.11,36.57 42.88,36.57
N68909145 on TOP (solid shape): 47.14,36.5 47.14,34.51 46.88,34.25 44.71,34.25 44.33,34.64 44.33,36.51 44.36,36.55 47.08,36.55
N68909145 on BOTTOM (solid shape): 47.06,37.38 47.06,34.38 46.81,34.13 40.47,34.13 40.2,34.4 40.2,37.31 40.4,37.51 46.94,37.51
N68909205 on TOP (solid shape): 51.33,36.51 51.33,34.63 50.95,34.25 48.52,34.25 48.41,34.37 48.41,36.41 48.53,36.54 51.29,36.54
N68909205 on TOP (solid shape): 55.52,36.5 55.52,34.51 55.26,34.25 53.09,34.25 52.71,34.64 52.71,36.5 52.73,36.52 55.49,36.52
N68909205 on BOTTOM (solid shape): 55.45,37.38 55.45,34.38 55.19,34.13 48.85,34.13 48.58,34.4 48.58,37.31 48.78,37.51 55.32,37.51
N77026396 on P09 (solid shape): 289.67,94.19 289.67,87.85 289.48,87.67 289.42,87.64 289.34,87.66 289.03,87.75 288.77,87.55 288.43,87.55 288.1,87.76 287.77,87.55 287.43,87.55 287.1,87.76 286.77,87.55 286.43,87.55 286.1,87.76 285.77,87.55 285.43,87.55 285.18,87.75 284.87,87.68 284.84,87.65 284.54,87.96 284.54,91.55 285.6,92.61 285.6,94.49 285.96,94.85 289,94.85
N77026454 on P09 (solid shape): 284.74,97.29 285.1,97.02 285.45,97.29 285.46,97.33 286.73,97.33 286.74,97.29 286.84,97.12 287.01,97.03 287.05,97.02 287.05,96.76 287.01,96.75 286.73,96.39 287.01,96.03 287.05,96.02 287.05,95.76 287.01,95.75 286.78,95.58 286.74,95.29 286.73,95.2 286.64,95.16 286.12,95.16 286.07,95.11 285.86,95.11 285.34,94.59 285.34,92.92 284.07,91.66 284.07,88.16 283.95,88.03 280.65,88.03 280.44,88.24 280.45,88.27 280.44,88.53 280.27,88.72 280.24,88.73 280.24,89.05 280.27,89.06 280.47,89.39 280.27,89.72 280.24,89.73 280.24,90.05 280.27,90.06 280.47,90.39 280.27,90.72 280.24,90.73 280.24,91.05 280.27,91.06 280.47,91.39 280.27,91.72 280.24,91.73 280.24,92.81 281.54,94.11 281.54,96.21 282.66,97.33 284.73,97.33
N79892105 on TOP (solid shape): 64.77,212.34 64.77,210.82 64.52,210.57 61.8,210.57 61.8,210.62 60.88,210.62 60.88,210.57 60.02,210.57 60.02,210.62 59.11,210.62 59.11,210.57 55.2,210.57 55.01,210.75 53.26,210.75 53.24,210.77 53.24,212.62 53.47,212.85 64.26,212.85

Small or netless copper shapes (teardrops, artwork), in the pictures only: 2 on TOP, 3 on BOTTOM, 4 on P12

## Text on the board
User.Comments: NOTES: UNLESS OTHERWISE SPECIFIED | 1. | 2. | 3. | 4. | 5. | 6. | 7. | ASSEMBLY WORKMANSHIP TO MEET OR EXCEED LATEST REVISION OF | IPC-A-610, CLASS 2. | AREA ARRAY PACKAGE SOLDER JOINT VOIDS TO MEET OR EXCEED LATEST REVISION OF | IPC-7095, CLASS 2. | THIS ASSEMBLY DRAWING SHOWS ALL COMPONENT LOCATIONS FOR ALL BOARD STUFF | OPTIONS.  REFER TO SPECIFIC BILL OF MATERIALS FOR COMPONENTS USED AND | SCHEMATIC. | REFER TO MANUFACTURING ASSEMBLY PROCEDURES (MAPs) LISTED ON THE BILL OF | MATERIALS. | SQUARE PADS INDICATE PIN NUMBER 1 THRU HOLE COMPONENTS, POSITIVE TERMINALS | OF POLARIZED CAPACITORS, CATHODES OF DIODES AND EMITTERS OF TRANSISTORS. | TRIM ALL THRU HOLE COMPONENT LEADS TO 0.085" MAXIMUM. | AFFIX SERIAL NUMBER LABEL IN DESIGNATED AREA AS SHOWN.
DIMENSION: 313.5 | 215.83
PAGE_OUTLINE: UNLESS OTHERWISE SPECIFIED | DIMENSIONS ARE IN INCHES | TOLERANCES ON; | 2 PL DECIMALS +/- .010 | 3 PL DECIMALS +/- .005 | ANGLES +/- 5 | FRACTIONS + | ISSUED | CAD    GRETA | ENGRG  HECTOR | SIGNATURES | 06.09.18 | DATE | SCALE | SIZE | FSCM NO | DWG NO | SHEET | REV | DESCRIPTION | REVISIONS | 1 TO 2 | APPROVED | D | T99O089T00 REV.025 | ASSY_TOP | PRIMARY SIDE | C | B | A | 7 | 6 | 5 | 4 | 3 | 2 | 1 | U | f | i | Space
User.6: NOTES: UNLESS OTHERWISE SPECIFIED | 14. | 13. | 12.ACCEPTABLE MINIMUN ANNULAR RING FOR VIA IS 0.001 | 15. | 17. | 16.FOR HIGH SPEED DIFF-PAIR WITH 98 OHMS IMPEDANCE, | 11. | 10. | 2. | 1. MATERIAL : TU883. THE USE OF SINGLE PLY CONSTRUCION IS OPTIONAL | 7. | 4. | 3 | 8. | 6. | 5. | 9. | THIS BOARD COMES WITH BACK DRILL PROCESS, SEE FAB03 FOR DETAILS OF BACK DRILL REQUIREMENT. | THE INSERTION LOSS SHOULD BE WELL CONTROLLED WITHIN 0.4dB/INCH @ 5GHz, 0.7dB/INCH @12.5GHz | NO DUMMY PAD IS ALLOWED ON THIS AREA. | SILKSCREEN TO BE WHITE. NON-CONDUCTIVE , EPOXY INK OR EQUIVALENT. | ALL FINISHED BOARDS MUST BE ELECTRICALLY TESTED AND PASS VENDOR TEST CRITIREA. | FAB VENDORS TO REMOVE ALL NON-FUNCTIONAL PADS. | EQUAL TO THE 0.003" COPPER WIDTH MUST BE ADDRESSED AND APPROVED IN WRITING. | IMPEDANCE SHALL BE 98 OHMS +/-8% ON ALL EXTERNAL LAYERS DIFFENTIAL PAIRS WITH 4.1MIL/6.4MIL WIDTH/SPACING. | IMPEDANCE SHALL BE 98 OHMS +/-8% ON ALL INTERNAL LAYERS DIFFENTIAL PAIRS WITH 4.2MIL/6.8MIL WIDTH/SPACING. | IMPEDANCE SHALL BE 90 OHMS +/-10% ON L3/L5/L7/L14/L16/L18 LAYERS DIFFENTIAL PAIRS WITH 5.0MIL/5.7MIL WIDTH/SPACING. | COPPER SLIVERS THAT ARE LESS THAN 0.003" IN WIDTH BETWEEN ANTI-PAD TO PLANE | EDGE, ANTI-PAD TO SPLIT PLANE, ANTI-PAD TO ANTI-PAD MUST BE REMOVED FROM THE | MANUFACTURING ARTWORK.  A NETLIST COMPARISON MUST PASS WITH NO VIOLATION | AFTER THE REMOVAL OF SLIVERS.  ANY REQUIREMENT FOR SLIVER REMOVAL ABOVE OR | IMPEDANCE SHALL BE 90 OHMS +/-10% ON ALL EXTERNAL LAYERS DIFFENTIAL PAIRS WITH 4.8MIL/5.2MIL WIDTH/SPACING. | THIS IS A 20 LAYER BOARD. VENDER TO PROVIDE BOARD STACK-UP FOR IMPEDANCE CONTROLLED. | APPROVAL PRIOR TO BOARD FABRICATION. | IMPEDANCE SHALL BE 50 OHMS +/-10% ON ALL EXTERNAL 0.0055 INCH TRACES. | IMPEDANCE SHALL BE 50 OHMS +/-10% ON L3/L5/L7/L14/L16/L18 LAYERS 0.0046 INCH TRACES. | SILKSCREEN BOARD USING SILKSCREEN MASTER ARTWORK. | SOLDERMASK BOTH SIDES OF BOARD WITH LIQUID PHOTO IMAGEABLE SOLDERMASK. | JOB NUMBER AND PCB MATERIAL UL FLAMMABILITY RATING (94V-0 MINIMUM). | TEST POINTS TO BE CLEAR OF SOLDERMASK. | VENDOR MUST BE UL QUALIFIED AND BOARDS MUST BE IDENTIFIED WITH | BASIC CONSTRUCTION SHALL BE SOLDERMASK OVER BARE COPPER (SMOBC). | APPROVAL. | APPROPRIATE VENDOR UL IDENTIFICATION MARK, DATE CODE, LOT OR | THIS IS A CONTROLLED IMPEDANCE BOARD.  CONTROLS ARE AS FOLLOWS: | FOR SMT COMPONENTS WITH PIN PITCH OF 0.020" OR MORE, NO "GANG RELIEF" | OF SOLDERMASK IS ALLOWED. | ALL COPPER FEATURES ON THE BOARD ARE TO BE FINISHED WITH OSP COAT. | FABRICATE USING MASTER ARTWORK T99O089T00 FOR CIRCUIT PATTERN. | NO DEVIATION FROM MASTER ARTWORK IS PERMITTED WITHOUT WRITTEN | 17
User.7: 3
User.8: 4pcs | 4Xdia0.125 +0.003 -0.000 Tooling hole | 4XR0.200 | Fiducial (See Detail A) | PRODUCT NAME | Xiao-wu Liu | SCALE | PREPARED | 1/1 | 2018/5/14 | DATE | REV. | 01 | FAB NO. | 0.200 | 0.000 | 0.293 | 8.883 | 9.283 | 9.083 | 8.653 | 8.560 | 8.790 | 0.619 | 0.712 | 0.744 | 0.651 | 0.449 | 0.356 | 0.300 | 1.720 | 2.020 | 3.461 | 3.761 | 5.661 | 5.961 | 7.361 | 7.661 | 9.361 | 9.661 | 11.642 | 11.643 | 11.743 | 11.942 | 11.943 | 12.143 | .120 DIA. Soldermask clearance | .040 DIA. Fiducial | UfiSpace DFM CENTER | T99O089T00 | PCB outline dimension detail see gerber file | Flow direction | Top side view | Detail "A" | Unit: inch
User.11: 2 TO 2 | ASSY_BOT | SECONDARY SIDE
User.13: 1 TO 2 | FABRICATION
User.15: 0.0040" | 0.0050" | 0.0080" | 0.00297" | 10% | LAYER #20 BOTTOM SIGNAL | BOTTOM SIDE SOLDERMASK | BOTTOM SIDE SILKSCREEN (WHITE) | TOP SIDE SILKSCREEN (WHITE) | TOP SIDE SOLDERMASK | LAYER #01 TOP SIGNAL | LAYER #02 G02 PLANE (1.0) | LAYER #03 T03 SIGNAL(1.0) | LAYER #04 G04 PLANE (1.0) | LAYER #05 T05 SIGNAL(1.0) | LAYER #06 G06 PLANE (1.0) | LAYER #07 T07 SIGNAL(1.0) | LAYER #08 G08 PLANEL(1.0) | LAYER #09 P09 PLANE (1.0) | LAYER #10 P10 PLANE (1.0) | LAYER #11 G11 PLANE (1.0) | LAYER #12 P12 PLANE (1.0) | LAYER #13 G13 PLANE (1.0) | LAYER #14 T14 SIGNAL(1.0) | LAYER #15 G15 PLANE (1.0) | LAYER #16 T16 SIGNAL(1.0) | LAYER #17 G17 PLANE (1.0) | LAYER #18 T18 SIGNAL(1.0) | LAYER #19 G19 PLANE (1.0) | (FOIL 0.5OZ+PLATING)-1.5 OZ) | + | - | 0.11764" | SCALE = NONE | XX | VIEW X-X
User.16: BOTTOM SIGNAL | 20
User.17: G02 GROUND | 2 | 20
User.18: T05 SIGNAL | 5 | 20
User.19: T07 SIGNAL | 7 | 20
User.20: G10 GROUND | 10 | 20
User.21: P12 POWER PLANE | 12 | 20
User.22: G15 GROUND | 15 | 20
User.23: G17 GROUND | 17 | 20
User.24: G19 GROUND | 19 | 20
User.25: G06 GROUND | 6 | 20
User.26: G11 GROUND | 11 | 20
User.27: PASTEMASK BOTTOM | 2
User.28: PASTEMASK TOP | 1 | 2
User.29: SOLDERMASK BOTTOM | 2
User.30: SOLDERMASK TOP | 1 | 2
User.31: SOLDER PROTECT BOTTOM | 2
User.32: SOLDER PROTECT TOP | 1
User.33: SILK SCREEN BOTTOM | 2
User.34: SILK SCREEN TOP | 1 | 2
User.35: T03 SIGNAL | 3 | 16
User.36: G04 GROUND | 4 | 20
User.37: G08 GROUND | 8 | 20
User.38: P09 POWER PLANE | 9 | 20
User.39: G13 GROUND | 13 | 20
User.40: T14 SIGNAL | 14 | 20
User.41: T16 SIGNAL | 16 | 20
User.42: T18 SIGNAL | 18 | 20
User.43: TOP SIGNAL | 1 | 20
User.45: NOTES: | - DRILL SIZES LISTED IN LEGEND | ARE CONSIDERED FINISHED. | - VENDOR IS REQUIRED TO SELECT | TOOLING FOR OVERDRILLING. | - LEGEND DOES NOT SPECIFY DEPTH | INTO ADJACENT DIELECTRIC LAYER. | 8.0 | 14.57 | 18.11 | 25.0 | +2.0/-5.0 | +2.0/-2.0 | +3.0/-3.0 | PLATED | 2 | 28 | 8 | 16 | 34 | 18 | 110 | 114 | 26 | 4 | 10.0 | 12.0 | 20.0 | 22.05 | 27.56 | 28.0 | 31.89 | 35.0 | 36.0 | 37.0 | 38.0 | 39.0 | 40.16 | 41.34 | 44.0 | 62.0 | 63.0 | 90.0 | 122.0 | 138.0 | 45.0 | 62.99 | 72.83 | 83.0 | 98.43 | 102.0 | 118.0 | 125.98 | 181.0 | 87.0x47.0 | +2.0/-7.0 | +1.18/-1.18 | +4.0/-4.0 | NON-PLATED | 10380 | 820 | 257 | 316 | 320 | 108 | 164 | 25 | 96 | 44 | 3 | 20 | 79 | 6 | 15 | 12 | 1 | LAYER | PROJECT | P/N:304.01088.025 | VER:025 | H/W | CAD | SHEET    OF | SIGNATURES | GRETA | HECTOR | DATE | SHEET | DWG NO | FSCM NO | SIZE | SCALE | 09.06.18 | CAD     GRETA | ENGRG   HECTOR | ISSUED | UNLESS OTHERWISE SPECIFIED | DIMENSIONS ARE IN INCHES | TOLERANCES ON; | 2 PL DECIMALS +/- .010 | 3 PL DECIMALS +/- .005 | ANGLES +/- 5 | FRACTIONS + | 06/09/18 | T99O089T00 | APPROVED | REVISIONS | DESCRIPTION | REV | FIGURE | FHS | TOLERANCE | ALL UNITS ARE IN MILS | QTY | BACKDRILL: TOP to G06 | BACKDRILL: BOTTOM to G08 | BACKDRILL: BOTTOM to G15 | BACKDRILL: TOP to G15 | BACKDRILL: BOTTOM to G17 | BACKDRILL: BOTTOM to G19 | BACKDRILL: TOP to G17 | DRILL CHART: TOP to BOTTOM | GERBER | D | B | C | A | 5 | 7 | U | f | i | Space
